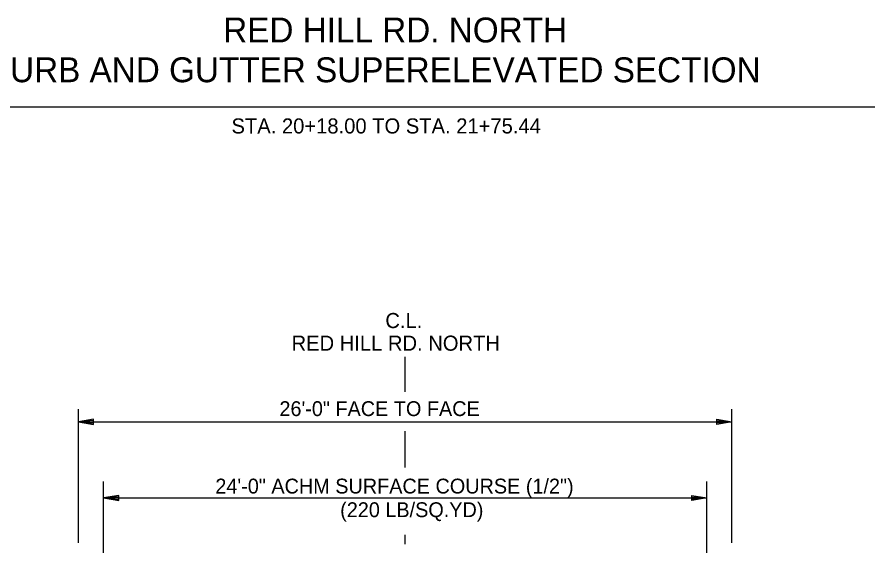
# Model space of a CAD drawing. Extents: x 1001270 to 1003428, y 1840152 to 1842912.
# Drawn here: x 1001325.08 to 1001359.21, y 1841312.25 to 1841333.28 of the extents above; entities that cross this region are included whole.
import ezdxf

# ---------------------------------------------------------------- set-up
doc = ezdxf.new("R2010")
doc.units = 0
doc.layers.add('19', color=7, linetype='Continuous')

msp = doc.modelspace()

# ---------------------------------------------------------------- linework, layer by layer
at = {"layer": '19'}
for p, q in [((1001359.207, 1841329.7), (1001323.061, 1841329.7)), ((1001340.517, 1841318.37), (1001340.517, 1841319.762)), ((1001327.518, 1841312.368), (1001327.518, 1841317.683)), ((1001353.522, 1841312.368), (1001353.522, 1841317.683)), ((1001328.118, 1841317.285), (1001327.518, 1841317.18)), ((1001327.518, 1841317.18), (1001353.522, 1841317.18)), ((1001327.518, 1841317.18), (1001328.118, 1841317.075)), ((1001328.118, 1841317.23), (1001327.678, 1841317.195)), ((1001327.678, 1841317.165), (1001328.118, 1841317.125)), ((1001328.118, 1841317.075), (1001328.118, 1841317.285)), ((1001352.921, 1841317.075), (1001352.921, 1841317.285)), ((1001352.921, 1841317.285), (1001353.522, 1841317.18)), ((1001352.921, 1841317.23), (1001353.362, 1841317.195)), ((1001353.522, 1841317.18), (1001352.921, 1841317.075)), ((1001353.362, 1841317.165), (1001352.921, 1841317.125)), ((1001340.517, 1841315.366), (1001340.517, 1841316.811)), ((1001328.517, 1841308.98), (1001328.517, 1841314.805)), ((1001352.521, 1841308.98), (1001352.521, 1841314.805)), ((1001328.517, 1841314.153), (1001352.521, 1841314.153)), ((1001329.118, 1841314.258), (1001328.518, 1841314.153)), ((1001328.518, 1841314.153), (1001329.118, 1841314.048)), ((1001329.118, 1841314.203), (1001328.678, 1841314.168)), ((1001328.678, 1841314.138), (1001329.118, 1841314.098)), ((1001329.118, 1841314.048), (1001329.118, 1841314.258)), ((1001351.921, 1841314.048), (1001351.921, 1841314.258)), ((1001351.921, 1841314.258), (1001352.521, 1841314.153)), ((1001351.921, 1841314.203), (1001352.361, 1841314.168)), ((1001352.521, 1841314.153), (1001351.921, 1841314.048)), ((1001352.361, 1841314.138), (1001351.921, 1841314.098)), ((1001340.517, 1841312.32), (1001340.517, 1841312.687))]:
    msp.add_line(p, q, dxfattribs=at)

# ---------------------------------------------------------------- texts
for s, height, rotation, p in [('RED HILL RD. NORTH', 0.98999, 359.9954, (1001333.277, 1841332.274)), ('CURB AND GUTTER SUPERELEVATED SECTION', 0.98999, 359.9954, (1001323.84, 1841330.69)), ('STA. 20+18.00 TO STA. 21+75.44', 0.6, 0.0046, (1001333.608, 1841328.65))]:
    msp.add_text(s, height=height, rotation=rotation, dxfattribs=at).set_placement(p)
for s, height, p in [('C.L.', 0.6, (1001339.729, 1841320.911)), ('RED HILL RD. NORTH', 0.6, (1001335.997, 1841320.011)), ('26\'-0" FACE TO FACE', 0.59001, (1001335.514, 1841317.411)), ('24\'-0" ACHM SURFACE COURSE (1/2")', 0.59001, (1001332.964, 1841314.331)), ('(220 LB/SQ.YD)', 0.59001, (1001337.931, 1841313.391))]:
    msp.add_text(s, height=height, dxfattribs=at).set_placement(p)

doc.saveas('drawing.dxf')
